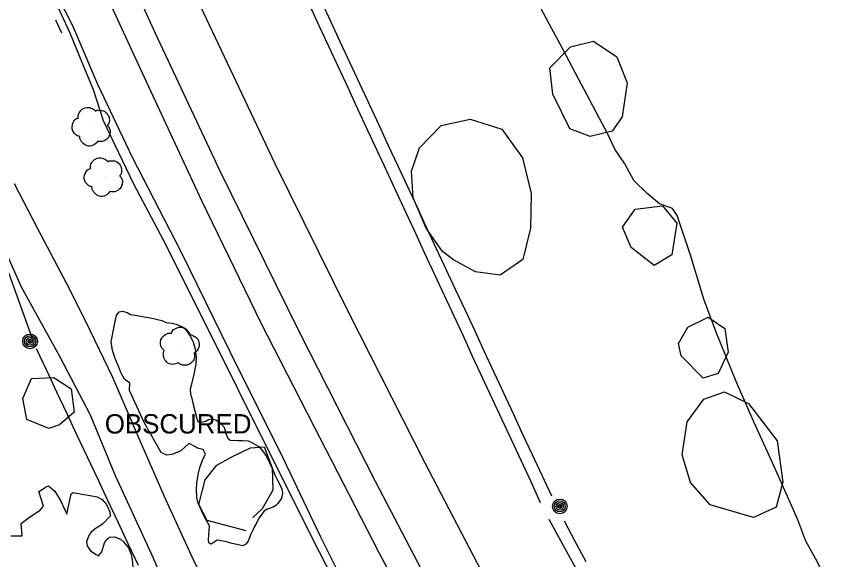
# Model space of a CAD drawing. Extents: x 368532 to 392481, y 10654822 to 10676899.
# Drawn here: x 376031.5 to 376245.5, y 10665609.3 to 10665749.7 of the extents above; entities that cross this region are included whole.
import ezdxf

# ---------------------------------------------------------------- set-up
doc = ezdxf.new("R2010")
doc.units = 0
for name, color, linetype in [('p_Catenary', 7, 'Continuous'), ('p_drainage culvert', 7, 'Continuous'), ('p_dtm obscured area', 7, 'Continuous'), ('p_dtm slab', 7, 'Continuous'), ('p_railroad rr control', 7, 'Continuous'), ('p_road dirt road', 7, 'Continuous'), ('p_structure fence', 7, 'Continuous'), ('p_utility general pole', 7, 'Continuous'), ('p_veg tree', 7, 'Continuous'), ('p_veg woods', 7, 'Continuous')]:
    doc.layers.add(name, color=color, linetype=linetype)

msp = doc.modelspace()

# ---------------------------------------------------------------- linework, layer by layer
at = {"layer": 'p_Catenary'}
for points in [[(376003.8, 10665755.13), (376005.78, 10665749.6), (376007.76, 10665744.07), (376009.75, 10665738.54), (376011.73, 10665733.01), (376013.71, 10665727.48), (376015.69, 10665721.96), (376017.68, 10665716.43), (376019.66, 10665710.9), (376021.64, 10665705.37), (376023.62, 10665699.84), (376025.61, 10665694.32), (376027.59, 10665688.79), (376029.57, 10665683.26), (376031.55, 10665677.73), (376033.54, 10665672.2), (376035.52, 10665666.68)], [(376169.86, 10665625.67), (376167.38, 10665631), (376164.9, 10665636.33), (376162.42, 10665641.66), (376159.94, 10665646.99), (376157.46, 10665652.33), (376154.98, 10665657.66), (376152.5, 10665662.99), (376150.02, 10665668.32), (376147.53, 10665673.65), (376145.05, 10665678.98), (376142.57, 10665684.31), (376140.09, 10665689.64), (376137.61, 10665694.97), (376135.13, 10665700.3), (376132.65, 10665705.63), (376130.17, 10665710.97), (376127.69, 10665716.3), (376125.21, 10665721.63), (376122.73, 10665726.96), (376120.25, 10665732.29), (376117.77, 10665737.62), (376115.29, 10665742.95), (376112.81, 10665748.28), (376110.33, 10665753.61)], [(376107.27, 10665752.61), (376109.75, 10665747.25), (376112.24, 10665741.9), (376114.72, 10665736.54), (376117.2, 10665731.19), (376119.69, 10665725.83), (376122.17, 10665720.48), (376124.66, 10665715.12), (376127.14, 10665709.77), (376129.63, 10665704.41), (376132.11, 10665699.06), (376134.6, 10665693.7), (376137.08, 10665688.35), (376139.57, 10665682.99), (376142.05, 10665677.64), (376144.53, 10665672.28), (376147.02, 10665666.93), (376149.5, 10665661.57), (376151.99, 10665656.22), (376154.47, 10665650.86), (376156.96, 10665645.51), (376159.44, 10665640.15), (376161.93, 10665634.8), (376164.41, 10665629.44), (376166.9, 10665624.09)], [(376036.61, 10665663.88), (376039.25, 10665658.27), (376041.88, 10665652.67), (376044.52, 10665647.06), (376047.16, 10665641.45), (376049.79, 10665635.85), (376052.43, 10665630.24), (376055.07, 10665624.64), (376057.71, 10665619.03), (376060.34, 10665613.42), (376062.98, 10665607.82)], [(376169.07, 10665619.78), (376171.57, 10665615.2), (376174.06, 10665610.62), (376176.56, 10665606.04)], [(376173.1, 10665619.33), (376175.86, 10665614.06), (376178.63, 10665608.79)]]:
    msp.add_lwpolyline(points, dxfattribs=at)
at = {"layer": 'p_drainage culvert'}
msp.add_line((376043.28, 10665745.41), (376041.68, 10665748.8), dxfattribs=at)
at = {"layer": 'p_dtm obscured area'}
msp.add_lwpolyline([(376080.38, 10665619.82), (376079.56, 10665621.4), (376078.93, 10665622.91), (376078.48, 10665623.9), (376078.13, 10665625.37), (376078.04, 10665627.41), (376078.12, 10665629.05), (376078.44, 10665631.28), (376078.88, 10665633.14), (376079.47, 10665634.75), (376080.01, 10665635.95), (376080.33, 10665636.51), (376079.79, 10665637.77), (376078.6, 10665638.02), (376077.43, 10665638.62), (376076.48, 10665639.17), (376076.1, 10665639.26), (376074.01, 10665637.38), (376071.7, 10665636.49), (376070.41, 10665636.29), (376068.93, 10665637), (376064.53, 10665644.76), (376060.75, 10665652.97), (376060.85, 10665654.87), (376059.43, 10665655.97), (376058.57, 10665657.53), (376057.97, 10665659.04), (376057.06, 10665661.27), (376056.35, 10665663.32), (376056, 10665665.58), (376056.6, 10665668.68), (376057, 10665670.89), (376057.33, 10665672.37), (376058.09, 10665673.35), (376058.95, 10665673.52), (376060.15, 10665673.15), (376060.97, 10665672.67), (376062.63, 10665672.36), (376063.64, 10665672.23), (376064.51, 10665672.08), (376066.15, 10665671.81), (376067.24, 10665671.54), (376067.95, 10665671.35), (376069.05, 10665671.1), (376070.18, 10665670.61), (376071.72, 10665670.44), (376072.82, 10665670.12), (376074.39, 10665669.46), (376075.2, 10665668.85), (376076.43, 10665667.08), (376077.07, 10665665.73), (376077.67, 10665663.78), (376077.93, 10665661.72), (376077.88, 10665659.93), (376077.41, 10665657.6), (376076.63, 10665654.34), (376076.42, 10665653.39), (376076.52, 10665652.06), (376076.74, 10665651.3), (376077.19, 10665649.42), (376077.57, 10665648.09), (376078.01, 10665646.12), (376078.22, 10665645.31), (376078.46, 10665644.93), (376079.19, 10665644.83), (376080.42, 10665645.09), (376081.16, 10665645.51), (376081.94, 10665645.68), (376083.02, 10665645.45), (376084.18, 10665644.66), (376085.19, 10665643.51), (376085.79, 10665641.5), (376086.14, 10665640.67), (376086.75, 10665640.13), (376088.72, 10665640.06), (376089.94, 10665640.05), (376091.38, 10665639.95), (376092.13, 10665639.67), (376092.97, 10665639.21), (376094.15, 10665638.51), (376095.12, 10665637.42), (376096.1, 10665635.92), (376096.99, 10665634.16), (376097.65, 10665632.69), (376098.19, 10665631.39), (376098.95, 10665629.81), (376099.54, 10665628.71), (376100.06, 10665627.51), (376100.27, 10665626.52), (376100.08, 10665625.49), (376099.89, 10665624.92), (376099.44, 10665624.31), (376099.06, 10665623.82), (376098.57, 10665623.28), (376097.87, 10665622.82), (376096.17, 10665622.22), (376095.42, 10665621.69), (376094.76, 10665620.79), (376094.18, 10665620), (376093.62, 10665618.87), (376093.04, 10665617.81), (376092.54, 10665616.73), (376092.06, 10665615.9), (376091.68, 10665614.73), (376091.41, 10665614.07), (376090.81, 10665613.3), (376090, 10665612.83), (376087.23, 10665613.48), (376085.42, 10665613.96), (376083.36, 10665614.27), (376082.09, 10665613.48), (376081.74, 10665613.28), (376081.27, 10665613.64), (376081.12, 10665614.36), (376081.41, 10665618.05)], close=True, dxfattribs=at)
msp.add_lwpolyline([(376030.16, 10665615.46), (376032.97, 10665615.44), (376032.77, 10665618.63), (376034.85, 10665620.29), (376037.63, 10665622.09), (376038.49, 10665623.08), (376037.32, 10665626.93), (376038.13, 10665627.43), (376039.01, 10665627.97), (376039.76, 10665628.33), (376041.47, 10665626.98), (376042.89, 10665624.58), (376044.53, 10665621.04), (376045.64, 10665626.3), (376046.18, 10665626.67), (376048.43, 10665626.23), (376050.58, 10665625.83), (376052.33, 10665625.48), (376053.65, 10665624.82), (376054.82, 10665623.57), (376055.61, 10665621.62), (376055.76, 10665620.54), (376053.79, 10665618.44), (376051.88, 10665617.28), (376050.82, 10665616.36), (376050.3, 10665615.66), (376049.64, 10665613.99), (376049.79, 10665612.8), (376050.66, 10665611.53), (376052.13, 10665610.57), (376052.75, 10665610.27), (376053.58, 10665611.3), (376054.23, 10665613.61), (376054.68, 10665614.36), (376055.55, 10665615.05), (376056.84, 10665615.16), (376058.44, 10665614.54), (376059.18, 10665613.85), (376060.44, 10665612.33), (376061.19, 10665610.6), (376061.46, 10665609.34), (376061.55, 10665607.25)], dxfattribs=at)
at = {"layer": 'p_dtm slab'}
for p, q in [((376169.19, 10665747.82), (376163.9, 10665757.71)), ((376172.67, 10665741.41), (376169.19, 10665747.82)), ((376175.99, 10665735.06), (376172.67, 10665741.41)), ((376184.37, 10665719.26), (376175.99, 10665735.06)), ((376186.18, 10665715.41), (376184.37, 10665719.26)), ((376188.76, 10665711.6), (376186.18, 10665715.41)), ((376191.06, 10665707.32), (376188.76, 10665711.6)), ((376194.52, 10665703.93), (376191.06, 10665707.32)), ((376197.67, 10665701.28), (376194.52, 10665703.93)), ((376201.03, 10665700.09), (376197.67, 10665701.28)), ((376202.27, 10665698.29), (376201.03, 10665700.09)), ((376205.78, 10665687.74), (376202.27, 10665698.29)), ((376209.17, 10665676.63), (376205.78, 10665687.74)), ((376212.34, 10665668.05), (376209.17, 10665676.63)), ((376217.51, 10665655.31), (376212.34, 10665668.05)), ((376222.09, 10665644.89), (376217.51, 10665655.31)), ((376227.76, 10665632.37), (376222.09, 10665644.89)), ((376233.41, 10665619.55), (376227.76, 10665632.37)), ((376235.52, 10665614.04), (376233.41, 10665619.55)), ((376238.05, 10665609.53), (376235.52, 10665614.04)), ((376245.49, 10665594.87), (376238.05, 10665609.53))]:
    msp.add_line(p, q, dxfattribs=at)
at = {"layer": 'p_railroad rr control'}
for points in [[(376216.67, 10665483.51), (376197.19, 10665520.27), (376178.65, 10665554.97), (376156.9, 10665596.42), (376137.16, 10665634.25), (376117.31, 10665673.24), (376098.33, 10665711.83), (376077.62, 10665755.55), (376056.45, 10665802.47), (376038.25, 10665845.1), (376032.08, 10665860.05)], [(376018.74, 10665855.38), (376032.08, 10665824.55), (376047.69, 10665788.61), (376067.36, 10665745.41), (376083.96, 10665709.98), (376104.52, 10665668.36), (376124.24, 10665629.54), (376153.01, 10665574.53), (376178.34, 10665526.32), (376202.43, 10665481.04)]]:
    msp.add_lwpolyline(points, dxfattribs=at)
at = {"layer": 'p_road dirt road'}
for p, q in [((376038.87, 10665761.19), (376046.04, 10665747.36)), ((376065.09, 10665732.84), (376051.83, 10665761.75)), ((376046.04, 10665747.36), (376052.46, 10665732.24)), ((376052.46, 10665732.24), (376061.46, 10665713.33)), ((376079.44, 10665702.03), (376065.09, 10665732.84)), ((376061.46, 10665713.33), (376073.97, 10665688.95)), ((376037.12, 10665694.67), (376031, 10665706.48)), ((376094.78, 10665670.44), (376079.44, 10665702.03)), ((376025.16, 10665696.82), (376032.71, 10665679.82)), ((376044.47, 10665680.72), (376037.12, 10665694.67)), ((376073.97, 10665688.95), (376086.65, 10665663.13)), ((376049.42, 10665670.82), (376044.47, 10665680.72)), ((376032.71, 10665679.82), (376042.64, 10665661.9)), ((376056.39, 10665656.37), (376049.42, 10665670.82)), ((376108.44, 10665643.68), (376094.78, 10665670.44)), ((376086.65, 10665663.13), (376100.36, 10665635.62)), ((376042.64, 10665661.9), (376050.53, 10665646.69)), ((376063.62, 10665639.55), (376056.39, 10665656.37)), ((376050.53, 10665646.69), (376057.02, 10665631.01)), ((376125.13, 10665611.2), (376108.44, 10665643.68)), ((376070.04, 10665624.99), (376063.62, 10665639.55)), ((376100.36, 10665635.62), (376110.1, 10665615.18)), ((376057.02, 10665631.01), (376066.73, 10665609.89)), ((376076.63, 10665610.52), (376070.04, 10665624.99)), ((376110.1, 10665615.18), (376121.27, 10665592.81)), ((376066.73, 10665609.89), (376076.08, 10665588.36)), ((376084.04, 10665594.96), (376076.63, 10665610.52)), ((376140.47, 10665582.64), (376125.13, 10665611.2))]:
    msp.add_line(p, q, dxfattribs=at)
at = {"layer": 'p_structure fence'}
for p, q in [((376045.38, 10665745.36), (376041.32, 10665754.2)), ((376048.65, 10665737.37), (376045.38, 10665745.36)), ((376051.41, 10665730.76), (376048.65, 10665737.37)), ((376054.05, 10665722.7), (376051.41, 10665730.76)), ((376061.83, 10665706.38), (376054.05, 10665722.7)), ((376069.5, 10665691.89), (376061.83, 10665706.38)), ((376081.56, 10665667.85), (376069.5, 10665691.89)), ((376096, 10665638.87), (376081.56, 10665667.85)), ((376109.74, 10665611.36), (376096, 10665638.87)), ((376121.45, 10665588.59), (376109.74, 10665611.36))]:
    msp.add_line(p, q, dxfattribs=at)
at = {"layer": 'p_utility general pole'}
for centre, radius in [((376035.04, 10665665.71), 1.9), ((376035.04, 10665665.71), 1.44), ((376035.04, 10665665.71), 0.973), ((376035.04, 10665665.71), 0.539), ((376035.04, 10665665.71), 0.192), ((376171.94, 10665623.05), 1.9), ((376171.94, 10665623.05), 1.44), ((376171.94, 10665623.05), 0.973), ((376171.94, 10665623.05), 0.539), ((376171.94, 10665623.05), 0.192)]:
    msp.add_circle(centre, radius, dxfattribs=at)
at = {"layer": 'p_veg tree'}
for p, q in [((376051.01, 10665721.34), (376051.01, 10665721.34)), ((376054.16, 10665708.31), (376054.16, 10665708.31)), ((376073.71, 10665664.32), (376073.71, 10665664.32))]:
    msp.add_line(p, q, dxfattribs=at)
for points in [[(376052.53, 10665717.47), (376051.37, 10665716.43), (376049.76, 10665716.3), (376048.51, 10665717.13), (376048.03, 10665717.84), (376047.88, 10665718.52), (376047.88, 10665718.67), (376047.77, 10665718.7), (376046.9, 10665719.11), (376045.89, 10665720.75), (376046.35, 10665722.61), (376047.38, 10665723.42), (376047.51, 10665723.47), (376047.5, 10665723.6), (376047.74, 10665724.79), (376048.85, 10665725.96), (376050.52, 10665726.14), (376051.5, 10665725.68), (376051.91, 10665725.31), (376051.97, 10665725.22), (376052.05, 10665725.29), (376052.7, 10665725.46), (376053.97, 10665725.3), (376055.17, 10665724.29), (376055.53, 10665722.95), (376055.23, 10665721.85), (376055.08, 10665721.63), (376055.08, 10665721.56), (376055.11, 10665721.51), (376055.37, 10665721.14), (376055.73, 10665720.23), (376055.55, 10665719.03), (376054.86, 10665717.98), (376053.37, 10665717.38), (376052.51, 10665717.46)], [(376055.68, 10665704.44), (376054.52, 10665703.41), (376052.91, 10665703.27), (376051.66, 10665704.11), (376051.18, 10665704.81), (376051.03, 10665705.5), (376051.03, 10665705.65), (376050.92, 10665705.68), (376050.05, 10665706.08), (376049.04, 10665707.73), (376049.5, 10665709.58), (376050.53, 10665710.39), (376050.66, 10665710.45), (376050.65, 10665710.57), (376050.89, 10665711.76), (376052, 10665712.93), (376053.67, 10665713.12), (376054.65, 10665712.65), (376055.06, 10665712.28), (376055.12, 10665712.19), (376055.2, 10665712.26), (376055.85, 10665712.43), (376057.12, 10665712.27), (376058.32, 10665711.27), (376058.68, 10665709.92), (376058.38, 10665708.82), (376058.23, 10665708.6), (376058.23, 10665708.53), (376058.26, 10665708.48), (376058.52, 10665708.11), (376058.88, 10665707.2), (376058.7, 10665706), (376058.01, 10665704.95), (376056.52, 10665704.36), (376055.66, 10665704.43)], [(376073.34, 10665660.17), (376071.84, 10665659.76), (376070.34, 10665660.36), (376069.59, 10665661.66), (376069.47, 10665662.51), (376069.64, 10665663.19), (376069.71, 10665663.32), (376069.63, 10665663.4), (376069.03, 10665664.15), (376068.86, 10665666.07), (376070.1, 10665667.53), (376071.37, 10665667.79), (376071.52, 10665667.78), (376071.56, 10665667.9), (376072.31, 10665668.86), (376073.82, 10665669.41), (376075.4, 10665668.84), (376076.07, 10665667.99), (376076.27, 10665667.48), (376076.29, 10665667.36), (376076.39, 10665667.39), (376077.05, 10665667.26), (376078.11, 10665666.55), (376078.75, 10665665.11), (376078.46, 10665663.75), (376077.71, 10665662.9), (376077.48, 10665662.77), (376077.44, 10665662.71), (376077.45, 10665662.65), (376077.52, 10665662.2), (376077.44, 10665661.22), (376076.74, 10665660.23), (376075.65, 10665659.6), (376074.06, 10665659.73), (376073.32, 10665660.17)]]:
    msp.add_spline(points, degree=3, dxfattribs=at)
at = {"layer": 'p_veg woods'}
for points in [[(376170.17, 10665729.61), (376169.37, 10665736.45), (376174.67, 10665741.87), (376180.6, 10665743.3), (376186.69, 10665739.32), (376189.33, 10665732.57), (376188.04, 10665723.81), (376185.46, 10665720.06), (376179.77, 10665718.68), (376174.56, 10665720.69)], [(376137.37, 10665694.96), (376134.02, 10665702.8), (376133.59, 10665709.71), (376135.67, 10665715.74), (376141.29, 10665721.53), (376148.8, 10665723.2), (376156.93, 10665720.56), (376162.33, 10665713.13), (376164.53, 10665703.98), (376164.35, 10665694.98), (376162.35, 10665686.9), (376156.51, 10665682.87), (376150.12, 10665683.65), (376144.48, 10665686.75), (376141.65, 10665688.97)], [(376190.36, 10665689.99), (376188.17, 10665695.2), (376191.38, 10665699.92), (376198.49, 10665700.78), (376202.19, 10665696.31), (376200.89, 10665688.1), (376196.34, 10665685.34)], [(376203.33, 10665662.01), (376202.64, 10665665.17), (376204.98, 10665669.4), (376210.26, 10665671.98), (376214.61, 10665669.08), (376215.46, 10665662.89), (376212.89, 10665657.37), (376208.99, 10665656.21)], [(376034.22, 10665645.48), (376033.17, 10665650.9), (376035.38, 10665656.15), (376041.21, 10665656.35), (376045.67, 10665653.42), (376046.4, 10665647.43), (376042.62, 10665644.09), (376039.89, 10665643.21)], [(376210.81, 10665623.45), (376205.69, 10665629.19), (376203.57, 10665636.36), (376204.88, 10665644.89), (376209.16, 10665650.73), (376214.46, 10665652.63), (376220.7, 10665649.68), (376228.08, 10665639.99), (376229.55, 10665629.32), (376227.82, 10665622.84), (376222, 10665620.18)]]:
    msp.add_lwpolyline(points, close=True, dxfattribs=at)
msp.add_lwpolyline([(376090.87, 10665616.72), (376087.93, 10665617.48), (376080.76, 10665619.35), (376078.62, 10665623.54), (376080.28, 10665629.95), (376083.29, 10665633.68), (376087.19, 10665635.88), (376092.01, 10665638.15), (376095.57, 10665638.48), (376097.56, 10665633.03), (376097.74, 10665627.23), (376095.01, 10665622.43), (376092.62, 10665620.17)], dxfattribs=at)

# ---------------------------------------------------------------- texts
at = {"layer": 'p_dtm obscured area'}
msp.add_text(' OBSCURED', height=5, dxfattribs=at).set_placement((376052.49, 10665641.89))

doc.saveas('drawing.dxf')
